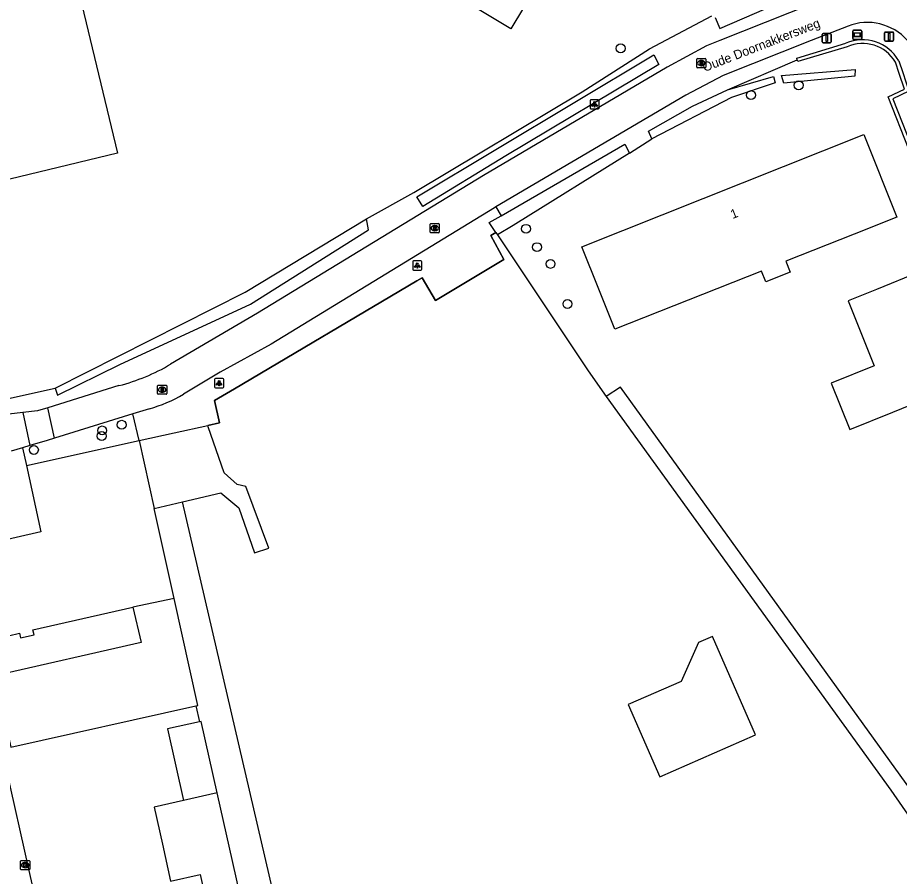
# Model space of a CAD drawing. Extents: x 164494 to 166241, y 382475 to 384494.
# Drawn here: x 164719.3 to 164815.9, y 383408.5 to 383502.5 of the extents above; entities that cross this region are included whole.
import ezdxf

# ---------------------------------------------------------------- set-up
doc = ezdxf.new("R2010")
doc.units = 0
for name, color, linetype in [('IMGEO_Afsluitpaal', 7, 'Continuous'), ('IMGEO_Boom', 7, 'Continuous'), ('IMGEO_Grasland_overig', 7, 'Continuous'), ('IMGEO_Groenvoorziening', 7, 'Continuous'), ('IMGEO_Haag', 7, 'Continuous'), ('IMGEO_Hek', 7, 'Continuous'), ('IMGEO_Kolk', 7, 'Continuous'), ('IMGEO_Lichtpunt', 7, 'Continuous'), ('IMGEO_Openbare_ruimte_label', 7, 'Continuous'), ('IMGEO_Pand', 7, 'Continuous'), ('IMGEO_Pand_nummerreeks', 7, 'Continuous'), ('IMGEO_Rijbaan_lokaal_open', 7, 'Continuous'), ('IMGEO_Rioolput', 7, 'Continuous'), ('IMGEO_Verklikker', 7, 'Continuous'), ('IMGEO_Voetpad_open', 7, 'Continuous'), ('IMGEO_Waterloop', 7, 'Continuous')]:
    doc.layers.add(name, color=color, linetype=linetype)

msp = doc.modelspace()

# ---------------------------------------------------------------- linework, layer by layer
at = {"layer": 'IMGEO_Afsluitpaal'}
for p, q in [((164807.533, 383500.752), (164808.323, 383500.752)), ((164808.323, 383500.752), (164807.533, 383500.752)), ((164814.269, 383500.022), (164814.269, 383500.822)), ((164814.269, 383500.822), (164814.269, 383500.022)), ((164814.369, 383500.922), (164815.159, 383500.922)), ((164815.159, 383500.922), (164814.369, 383500.922)), ((164815.259, 383500.822), (164815.259, 383500.022)), ((164815.259, 383500.022), (164815.259, 383500.822)), ((164807.433, 383499.852), (164807.433, 383500.652)), ((164807.433, 383500.652), (164807.433, 383499.852)), ((164808.423, 383500.652), (164808.423, 383499.852)), ((164808.423, 383499.852), (164808.423, 383500.652)), ((164815.159, 383499.922), (164814.369, 383499.922)), ((164814.369, 383499.922), (164815.159, 383499.922)), ((164808.323, 383499.752), (164807.533, 383499.752)), ((164807.533, 383499.752), (164808.323, 383499.752))]:
    msp.add_line(p, q, dxfattribs=at)
for points in [[(164814.689, 383500.797), (164814.839, 383500.797), (164814.839, 383500.047), (164814.689, 383500.047), (164814.689, 383500.797)], [(164807.853, 383500.627), (164808.003, 383500.627), (164808.003, 383499.877), (164807.853, 383499.877), (164807.853, 383500.627)]]:
    msp.add_lwpolyline(points, dxfattribs=at)
for centre, start, end in [((164807.533, 383500.652), 90, 180), ((164807.533, 383500.652), 90, 180), ((164808.323, 383500.652), 0, 90), ((164808.323, 383500.652), 360, 90), ((164814.369, 383500.822), 90, 180), ((164814.369, 383500.822), 90, 180), ((164815.159, 383500.822), 0, 90), ((164815.159, 383500.822), 360, 90), ((164807.533, 383499.852), 180, 270), ((164807.533, 383499.852), 180, 270), ((164808.323, 383499.852), 270, 0), ((164808.323, 383499.852), 270, 0), ((164814.369, 383500.022), 180, 270), ((164814.369, 383500.022), 180, 270), ((164815.159, 383500.022), 270, 0), ((164815.159, 383500.022), 270, 0)]:
    msp.add_arc(centre, 0.1, start, end, dxfattribs=at)
at = {"layer": 'IMGEO_Boom'}
for centre in [(164785.363, 383499.133), (164804.856, 383495.089), (164799.632, 383494.011), (164775.003, 383479.372), (164776.197, 383477.362), (164777.682, 383475.53), (164779.54, 383471.137), (164730.724, 383457.909), (164728.584, 383457.288), (164728.54, 383456.679), (164721.106, 383455.158)]:
    msp.add_circle(centre, 0.489, dxfattribs=at)
at = {"layer": 'IMGEO_Grasland_overig'}
for points in [[(164867.478, 383349.751), (164820.036, 383413.911), (164785.335, 383462.011), (164783.794, 383461.004)], [(164783.794, 383461.004), (164814.936, 383417.889), (164860.759, 383351.899)], [(164750.963, 383391.02), (164737.368, 383449.485)], [(164738.851, 383427.135), (164739.244, 383425.389)]]:
    msp.add_lwpolyline(points, dxfattribs=at)
at = {"layer": 'IMGEO_Groenvoorziening'}
for points in [[(164757.54, 383480.473), (164762.712, 383483.342), (164781.141, 383494.371), (164788.505, 383499.077), (164795.364, 383502.697)], [(164797.054, 383494.584), (164804.71, 383497.863)], [(164786.318, 383487.654), (164788.789, 383489.23)], [(164771.873, 383478.714), (164781.789, 383463.825), (164783.794, 383461.004)], [(164662.344, 383448.801), (164663.225, 383448.827), (164664.07, 383448.843), (164665.63, 383449.11), (164723.453, 383461.907)], [(164719.856, 383455.391), (164720.284, 383453.449)]]:
    msp.add_lwpolyline(points, dxfattribs=at)
at = {"layer": 'IMGEO_Haag'}
for points in [[(164804.71, 383497.863), (164804.648, 383498.068), (164810.02, 383499.694)], [(164810.159, 383499.318), (164804.764, 383497.685), (164804.71, 383497.863)], [(164817.327, 383479.981), (164817.068, 383480.286), (164819.267, 383482.152), (164814.665, 383493.821), (164816.44, 383494.67), (164815.874, 383496.362), (164815.456, 383497.612)], [(164815.822, 383497.777), (164816.253, 383496.489), (164816.931, 383494.462), (164815.174, 383493.621), (164819.744, 383482.032), (164817.327, 383479.981)]]:
    msp.add_lwpolyline(points, dxfattribs=at)
for centre, radius, start, end in [((164811.851, 383495.498), 4.578, 29.85172, 113.58083), ((164811.852, 383495.497), 4.179, 30.40254, 113.89317)]:
    msp.add_arc(centre, radius, start, end, dxfattribs=at)
at = {"layer": 'IMGEO_Hek'}
msp.add_lwpolyline([(164771.699, 383478.975), (164771.151, 383478.63), (164772.583, 383475.997), (164765.09, 383471.534), (164763.63, 383474.017), (164763.042, 383473.669), (164743.085, 383461.862), (164740.895, 383460.566), (164741.434, 383458.132), (164740.154, 383457.849)], dxfattribs=at)
at = {"layer": 'IMGEO_Kolk'}
for p, q in [((164719.648, 383409.262), (164719.648, 383410.114)), ((164719.723, 383410.188), (164720.575, 383410.188)), ((164720.649, 383410.114), (164720.649, 383409.262)), ((164720.575, 383409.188), (164719.723, 383409.188)), ((164720.159, 383409.408), (164720.134, 383409.408)), ((164720.136, 383409.968), (164720.161, 383409.968))]:
    msp.add_line(p, q, dxfattribs=at)
for points in [[(164719.648, 383409.262), (164719.648, 383410.114)], [(164719.723, 383410.188), (164720.575, 383410.188)], [(164720.649, 383410.114), (164720.649, 383409.262)], [(164720.575, 383409.188), (164719.723, 383409.188)], [(164719.969, 383409.888), (164720.092, 383409.888), (164720.092, 383409.737), (164720.222, 383409.888), (164720.386, 383409.888), (164720.24, 383409.737), (164720.393, 383409.488), (164720.241, 383409.488), (164720.156, 383409.652), (164720.092, 383409.585), (164720.092, 383409.488), (164719.969, 383409.488), (164719.969, 383409.888)]]:
    msp.add_lwpolyline(points, dxfattribs=at)
for centre, start, end in [((164719.725, 383410.112), 91.55205, 178.44795), ((164719.725, 383410.112), 91.55205, 178.44795), ((164720.573, 383410.112), 1.55205, 88.44795), ((164720.573, 383410.112), 1.55205, 88.44795), ((164719.725, 383409.264), 181.55205, 268.44795), ((164719.725, 383409.264), 181.55205, 268.44795), ((164720.573, 383409.264), 271.55205, 358.44795), ((164720.573, 383409.264), 271.55205, 358.44795)]:
    msp.add_arc(centre, 0.0765, start, end, dxfattribs=at)
for centre, major_axis, ratio, start_param, end_param in [((164720.135, 383409.688), (-0.387, 0.002), 0.722429, 4.712389, 7.853982), ((164720.16, 383409.688), (-0.39, 0.002), 0.717154, 1.570796, 4.712389)]:
    msp.add_ellipse(centre, major_axis=major_axis, ratio=ratio, start_param=start_param, end_param=end_param, dxfattribs=at)
at = {"layer": 'IMGEO_Lichtpunt'}
for p, q in [((164782.01, 383493.405), (164782.01, 383492.598)), ((164782.01, 383493.405), (164782.01, 383492.598)), ((164782.912, 383493.5), (164782.104, 383493.5)), ((164782.912, 383493.5), (164782.104, 383493.5)), ((164783.006, 383492.598), (164783.006, 383493.405)), ((164783.006, 383492.598), (164783.006, 383493.405)), ((164782.104, 383492.504), (164782.912, 383492.504)), ((164782.104, 383492.504), (164782.912, 383492.504)), ((164762.595, 383475.755), (164762.595, 383474.948)), ((164762.595, 383475.755), (164762.595, 383474.948)), ((164763.497, 383475.85), (164762.689, 383475.85)), ((164763.497, 383475.85), (164762.689, 383475.85)), ((164763.591, 383474.948), (164763.591, 383475.755)), ((164763.591, 383474.948), (164763.591, 383475.755)), ((164762.689, 383474.854), (164763.497, 383474.854)), ((164762.689, 383474.854), (164763.497, 383474.854)), ((164740.894, 383462.866), (164740.894, 383462.059)), ((164740.894, 383462.866), (164740.894, 383462.059)), ((164741.796, 383462.961), (164740.988, 383462.961)), ((164741.796, 383462.961), (164740.988, 383462.961)), ((164741.89, 383462.059), (164741.89, 383462.866)), ((164741.89, 383462.059), (164741.89, 383462.866)), ((164740.988, 383461.965), (164741.796, 383461.965)), ((164740.988, 383461.965), (164741.796, 383461.965))]:
    msp.add_line(p, q, dxfattribs=at)
for points in [[(164782.384, 383493.069), (164782.423, 383493.041), (164782.235, 383492.779), (164782.197, 383492.806), (164782.384, 383493.069)], [(164782.596, 383493.041), (164782.634, 383493.068), (164782.821, 383492.806), (164782.782, 383492.778), (164782.596, 383493.041)], [(164782.486, 383493.021), (164782.533, 383493.021), (164782.533, 383492.699), (164782.486, 383492.699), (164782.486, 383493.021)], [(164762.969, 383475.419), (164763.008, 383475.391), (164762.82, 383475.129), (164762.782, 383475.156), (164762.969, 383475.419)], [(164763.071, 383475.371), (164763.118, 383475.371), (164763.118, 383475.049), (164763.071, 383475.049), (164763.071, 383475.371)], [(164763.181, 383475.391), (164763.219, 383475.418), (164763.406, 383475.156), (164763.367, 383475.128), (164763.181, 383475.391)], [(164741.268, 383462.53), (164741.307, 383462.502), (164741.119, 383462.24), (164741.081, 383462.267), (164741.268, 383462.53)], [(164741.37, 383462.482), (164741.417, 383462.482), (164741.417, 383462.16), (164741.37, 383462.16), (164741.37, 383462.482)], [(164741.48, 383462.502), (164741.518, 383462.529), (164741.705, 383462.267), (164741.666, 383462.239), (164741.48, 383462.502)]]:
    msp.add_lwpolyline(points, dxfattribs=at)
for centre in [(164782.509, 383493.203), (164763.094, 383475.553), (164741.393, 383462.664)]:
    msp.add_circle(centre, 0.0994, dxfattribs=at)
for centre, start, end in [((164782.104, 383493.405), 90, 180), ((164782.104, 383493.405), 90, 180), ((164782.912, 383493.405), 0, 90), ((164782.912, 383493.405), 0, 90), ((164782.104, 383492.598), 180, 270), ((164782.104, 383492.598), 180, 270), ((164782.912, 383492.598), 270, 0), ((164782.912, 383492.598), 270, 360), ((164762.689, 383475.755), 90, 180), ((164762.689, 383475.755), 90, 180), ((164763.497, 383475.755), 0, 90), ((164763.497, 383475.755), 0, 90), ((164762.689, 383474.948), 180, 270), ((164762.689, 383474.948), 180, 270), ((164763.497, 383474.948), 270, 0), ((164763.497, 383474.948), 270, 360), ((164740.988, 383462.866), 90, 180), ((164740.988, 383462.866), 90, 180), ((164741.796, 383462.866), 0, 90), ((164741.796, 383462.866), 0, 90), ((164740.988, 383462.059), 180, 270), ((164740.988, 383462.059), 180, 270), ((164741.796, 383462.059), 270, 0), ((164741.796, 383462.059), 270, 360)]:
    msp.add_arc(centre, 0.0946, start, end, dxfattribs=at)
at = {"layer": 'IMGEO_Pand'}
for points in [[(164730.267, 383487.654), (164656.027, 383469.749), (164647.473, 383505.183), (164721.758, 383523.074), (164730.267, 383487.654)], [(164776.262, 383522.425), (164783.449, 383518.106), (164779.823, 383512.072), (164773.337, 383501.281), (164766.151, 383505.6), (164776.262, 383522.425)], [(164810.948, 383478.786), (164803.466, 383475.813), (164803.938, 383474.624), (164801.265, 383473.562), (164800.793, 383474.75), (164784.725, 383468.365), (164782.975, 383472.768), (164781.129, 383477.414), (164811.998, 383489.681), (164815.594, 383480.632), (164810.948, 383478.786)], [(164818.028, 383474.606), (164813.393, 383472.732), (164810.263, 383471.466), (164813.128, 383464.38), (164808.413, 383462.473), (164810.468, 383457.391), (164815.183, 383459.298), (164818.313, 383460.564), (164822.948, 383462.439), (164818.103, 383474.421)], [(164720.284, 383453.449), (164732.618, 383456.18)], [(164732.618, 383456.18), (164734.264, 383448.756)], [(164720.284, 383453.449), (164721.882, 383446.198), (164713.732, 383444.341), (164715.87, 383434.212), (164719.515, 383435.099), (164719.645, 383434.565), (164721.137, 383434.904), (164721.007, 383435.439), (164731.927, 383437.925)], [(164736.451, 383438.887), (164734.264, 383448.756)], [(164736.451, 383438.887), (164731.927, 383437.925)], [(164738.851, 383427.135), (164739.046, 383427.179), (164736.451, 383438.887)], [(164731.927, 383437.925), (164732.868, 383434.058), (164716.799, 383430.411), (164718.579, 383422.594), (164738.851, 383427.135)], [(164800.139, 383423.943), (164795.427, 383434.732), (164793.899, 383434.065), (164791.981, 383429.793), (164786.184, 383427.262), (164789.637, 383419.356), (164800.139, 383423.943)], [(164739.244, 383425.389), (164735.737, 383424.619), (164737.491, 383416.761)], [(164741.194, 383417.588), (164739.434, 383425.431), (164739.244, 383425.389)], [(164737.491, 383416.761), (164734.27, 383416.042), (164735.174, 383411.992), (164736.078, 383407.942), (164739.299, 383408.66), (164740.892, 383401.524)], [(164741.194, 383417.588), (164737.491, 383416.761)], [(164744.613, 383402.354), (164741.194, 383417.588)]]:
    msp.add_lwpolyline(points, dxfattribs=at)
at = {"layer": 'IMGEO_Rijbaan_lokaal_open'}
for points in [[(164808.828, 383505.036), (164796.221, 383500), (164794.753, 383499.407), (164790.471, 383497.065), (164770.361, 383485.201), (164745.588, 383470.135), (164736.073, 383464.54)], [(164810.262, 383501.572), (164806.227, 383500), (164796.587, 383496.145), (164792.485, 383494.012), (164771.708, 383481.781)], [(164771.708, 383481.781), (164771.534, 383481.679), (164747.101, 383466.722), (164741.488, 383463.681), (164737.479, 383461.248)], [(164730.422, 383462.201), (164722.622, 383459.776)], [(164719.895, 383459.238), (164717.739, 383458.983), (164712.427, 383457.585), (164708.916, 383456.753), (164693.004, 383452.936), (164678.342, 383449.582), (164665.421, 383446.666)], [(164722.622, 383459.776), (164721.503, 383459.428), (164719.895, 383459.238)], [(164719.895, 383459.238), (164720.68, 383455.635)], [(164723.35, 383456.437), (164722.622, 383459.776)], [(164733.751, 383459.673), (164731.926, 383459.105)], [(164731.926, 383459.105), (164723.35, 383456.437)], [(164723.35, 383456.437), (164722.557, 383456.19), (164720.68, 383455.635)], [(164719.856, 383455.391), (164718.625, 383455.027)], [(164720.68, 383455.635), (164719.856, 383455.391)], [(164704.135, 383380.45), (164714.062, 383382.757), (164725.993, 383385.33), (164723.274, 383397.213), (164720.675, 383408.755), (164718.016, 383420.672)]]:
    msp.add_lwpolyline(points, dxfattribs=at)
for centre, radius, start, end in [((164812.384, 383496.117), 5.853, 41.62554, 111.25429), ((164724.919, 383483.492), 21.991, 284.49179, 300.47843), ((164729.888, 383474.017), 14.855, 285.07406, 300.73197)]:
    msp.add_arc(centre, radius, start, end, dxfattribs=at)
at = {"layer": 'IMGEO_Rioolput'}
for p, q in [((164793.696, 383497.09), (164793.696, 383497.942)), ((164793.771, 383498.016), (164794.623, 383498.016)), ((164794.697, 383497.942), (164794.697, 383497.09)), ((164794.623, 383497.016), (164793.771, 383497.016)), ((164794.207, 383497.236), (164794.182, 383497.236)), ((164794.184, 383497.796), (164794.209, 383497.796)), ((164764.504, 383479.016), (164764.504, 383479.868)), ((164764.579, 383479.942), (164765.431, 383479.942)), ((164764.992, 383479.722), (164765.017, 383479.722)), ((164765.505, 383479.868), (164765.505, 383479.016)), ((164765.431, 383478.942), (164764.579, 383478.942)), ((164765.015, 383479.162), (164764.99, 383479.162)), ((164734.657, 383461.319), (164734.657, 383462.171)), ((164734.732, 383462.245), (164735.584, 383462.245)), ((164735.658, 383462.171), (164735.658, 383461.319)), ((164735.584, 383461.245), (164734.732, 383461.245)), ((164735.168, 383461.465), (164735.143, 383461.465)), ((164735.145, 383462.025), (164735.17, 383462.025))]:
    msp.add_line(p, q, dxfattribs=at)
for points in [[(164793.696, 383497.09), (164793.696, 383497.942)], [(164793.771, 383498.016), (164794.623, 383498.016)], [(164794.697, 383497.942), (164794.697, 383497.09)], [(164794.623, 383497.016), (164793.771, 383497.016)], [(164794.285, 383497.714), (164794.033, 383497.716), (164794.033, 383497.316)], [(164794.033, 383497.316), (164794.157, 383497.316), (164794.157, 383497.478), (164794.168, 383497.478)], [(164794.211, 383497.635), (164794.157, 383497.635), (164794.157, 383497.554)], [(164794.157, 383497.554), (164794.209, 383497.554)], [(164794.215, 383497.449), (164794.286, 383497.316), (164794.426, 383497.316), (164794.361, 383497.442)], [(164764.504, 383479.016), (164764.504, 383479.868)], [(164764.579, 383479.942), (164765.431, 383479.942)], [(164765.093, 383479.64), (164764.841, 383479.642), (164764.841, 383479.242)], [(164765.019, 383479.561), (164764.965, 383479.561), (164764.965, 383479.48)], [(164765.505, 383479.868), (164765.505, 383479.016)], [(164765.431, 383478.942), (164764.579, 383478.942)], [(164764.841, 383479.242), (164764.965, 383479.242), (164764.965, 383479.404), (164764.976, 383479.404)], [(164764.965, 383479.48), (164765.017, 383479.48)], [(164765.023, 383479.375), (164765.094, 383479.242), (164765.234, 383479.242), (164765.169, 383479.368)], [(164734.657, 383461.319), (164734.657, 383462.171)], [(164734.732, 383462.245), (164735.584, 383462.245)], [(164735.658, 383462.171), (164735.658, 383461.319)], [(164735.584, 383461.245), (164734.732, 383461.245)], [(164735.246, 383461.943), (164734.994, 383461.945), (164734.994, 383461.545)], [(164734.994, 383461.545), (164735.118, 383461.545), (164735.118, 383461.707), (164735.129, 383461.707)], [(164735.172, 383461.864), (164735.118, 383461.864), (164735.118, 383461.783)], [(164735.118, 383461.783), (164735.17, 383461.783)], [(164735.176, 383461.678), (164735.247, 383461.545), (164735.387, 383461.545), (164735.322, 383461.671)]]:
    msp.add_lwpolyline(points, dxfattribs=at)
for centre, radius, start, end in [((164793.773, 383497.94), 0.0765, 91.55205, 178.44795), ((164793.773, 383497.94), 0.0765, 91.55205, 178.44795), ((164794.621, 383497.94), 0.0765, 1.55205, 88.44795), ((164794.621, 383497.94), 0.0765, 1.55205, 88.44795), ((164793.773, 383497.092), 0.0765, 181.55205, 268.44795), ((164793.773, 383497.092), 0.0765, 181.55205, 268.44795), ((164794.167, 383497.425), 0.0533, 26.02933, 88.69889), ((164794.193, 383497.743), 0.19, 274.7715, 282.96867), ((164794.217, 383497.539), 0.0964, 77.00612, 93.18647), ((164794.231, 383497.596), 0.0378, 276.66336, 79.67722), ((164794.284, 383497.604), 0.109, 350.36119, 89.41601), ((164794.282, 383497.604), 0.112, 277.58423, 350.98172), ((164794.266, 383497.389), 0.108, 29.51342, 73.79051), ((164794.621, 383497.092), 0.0765, 271.55205, 358.44795), ((164794.621, 383497.092), 0.0765, 271.55205, 358.44795), ((164764.581, 383479.866), 0.0765, 91.55205, 178.44795), ((164764.581, 383479.866), 0.0765, 91.55205, 178.44795), ((164765.025, 383479.465), 0.0964, 77.00612, 93.18647), ((164765.039, 383479.522), 0.0378, 276.66336, 79.67722), ((164765.092, 383479.53), 0.109, 350.36119, 89.41601), ((164765.09, 383479.53), 0.112, 277.58423, 350.98172), ((164765.429, 383479.866), 0.0765, 1.55205, 88.44795), ((164765.429, 383479.866), 0.0765, 1.55205, 88.44795), ((164764.581, 383479.018), 0.0765, 181.55205, 268.44795), ((164764.581, 383479.018), 0.0765, 181.55205, 268.44795), ((164764.975, 383479.351), 0.0533, 26.02933, 88.69889), ((164765.001, 383479.669), 0.19, 274.7715, 282.96867), ((164765.074, 383479.315), 0.108, 29.51342, 73.79051), ((164765.429, 383479.018), 0.0765, 271.55205, 358.44795), ((164765.429, 383479.018), 0.0765, 271.55205, 358.44795), ((164734.734, 383462.169), 0.0765, 91.55205, 178.44795), ((164734.734, 383462.169), 0.0765, 91.55205, 178.44795), ((164735.582, 383462.169), 0.0765, 1.55205, 88.44795), ((164735.582, 383462.169), 0.0765, 1.55205, 88.44795), ((164734.734, 383461.321), 0.0765, 181.55205, 268.44795), ((164734.734, 383461.321), 0.0765, 181.55205, 268.44795), ((164735.128, 383461.654), 0.0533, 26.02933, 88.69889), ((164735.154, 383461.972), 0.19, 274.7715, 282.96867), ((164735.178, 383461.768), 0.0964, 77.00612, 93.18647), ((164735.192, 383461.825), 0.0378, 276.66336, 79.67722), ((164735.245, 383461.833), 0.109, 350.36119, 89.41601), ((164735.243, 383461.833), 0.112, 277.58423, 350.98172), ((164735.227, 383461.618), 0.108, 29.51342, 73.79051), ((164735.582, 383461.321), 0.0765, 271.55205, 358.44795), ((164735.582, 383461.321), 0.0765, 271.55205, 358.44795)]:
    msp.add_arc(centre, radius, start, end, dxfattribs=at)
for centre, major_axis, ratio, start_param, end_param in [((164794.183, 383497.516), (-0.387, 0.002), 0.722429, 4.712389, 7.853982), ((164794.208, 383497.516), (-0.39, 0.002), 0.717154, 1.570796, 4.712389), ((164764.991, 383479.442), (-0.387, 0.002), 0.722429, 4.712389, 7.853982), ((164765.016, 383479.442), (-0.39, 0.002), 0.717154, 1.570796, 4.712389), ((164735.144, 383461.745), (-0.387, 0.002), 0.722429, 4.712389, 7.853982), ((164735.169, 383461.745), (-0.39, 0.002), 0.717154, 1.570796, 4.712389)]:
    msp.add_ellipse(centre, major_axis=major_axis, ratio=ratio, start_param=start_param, end_param=end_param, dxfattribs=at)
at = {"layer": 'IMGEO_Verklikker'}
for p, q in [((164810.777, 383500.218), (164810.777, 383501.018)), ((164810.777, 383501.018), (164810.777, 383500.218)), ((164810.877, 383501.118), (164811.667, 383501.118)), ((164811.667, 383501.118), (164810.877, 383501.118)), ((164811.767, 383501.018), (164811.767, 383500.218)), ((164811.767, 383500.218), (164811.767, 383501.018)), ((164811.667, 383500.118), (164810.877, 383500.118)), ((164810.877, 383500.118), (164811.667, 383500.118))]:
    msp.add_line(p, q, dxfattribs=at)
for points in [[(164810.878, 383500.85), (164811.666, 383500.85), (164811.666, 383500.386), (164810.878, 383500.386), (164810.878, 383500.85)], [(164810.943, 383500.785), (164810.943, 383500.451), (164811.601, 383500.451), (164811.601, 383500.785), (164810.943, 383500.785)]]:
    msp.add_lwpolyline(points, dxfattribs=at)
for centre, start, end in [((164810.877, 383501.018), 90, 180), ((164810.877, 383501.018), 90, 180), ((164811.667, 383501.018), 0, 90), ((164811.667, 383501.018), 360, 90), ((164810.877, 383500.218), 180, 270), ((164810.877, 383500.218), 180, 270), ((164811.667, 383500.218), 270, 0), ((164811.667, 383500.218), 270, 0)]:
    msp.add_arc(centre, 0.1, start, end, dxfattribs=at)
at = {"layer": 'IMGEO_Voetpad_open'}
for points in [[(164771.708, 383481.781), (164772.275, 383480.798)], [(164771.699, 383478.975), (164770.982, 383480.051), (164772.275, 383480.798)], [(164740.154, 383457.849), (164741.434, 383458.132), (164740.895, 383460.566), (164743.085, 383461.862), (164763.042, 383473.669), (164763.63, 383474.017), (164765.09, 383471.534), (164772.583, 383475.997), (164771.151, 383478.63), (164771.699, 383478.975)], [(164732.618, 383456.18), (164731.926, 383459.105)], [(164732.618, 383456.18), (164736.455, 383457.03), (164740.154, 383457.849)], [(164737.368, 383449.485), (164741.582, 383450.474), (164743.549, 383448.824), (164745.27, 383443.883), (164746.846, 383444.411), (164744.321, 383451.166), (164743.354, 383451.363), (164741.949, 383452.648), (164740.206, 383457.698), (164740.154, 383457.849)], [(164734.264, 383448.756), (164737.368, 383449.485)]]:
    msp.add_lwpolyline(points, dxfattribs=at)
at = {"layer": 'IMGEO_Waterloop'}
for points in [[(164795.697, 383502.499), (164796.236, 383501.305), (164808.959, 383506.852)], [(164763.702, 383481.825), (164763.059, 383482.881), (164788.979, 383498.441), (164789.529, 383497.361), (164772.799, 383487.358), (164763.702, 383481.825)], [(164797.054, 383494.584), (164802.084, 383496.046), (164802.293, 383495.345), (164797.502, 383493.764), (164788.789, 383489.23)], [(164803.242, 383495.324), (164802.984, 383496.166), (164811.041, 383496.811), (164811.02, 383496.072), (164803.242, 383495.324)], [(164788.789, 383489.23), (164788.407, 383490.058), (164793.213, 383492.801), (164797.054, 383494.584)], [(164772.275, 383480.798), (164785.82, 383488.625), (164786.318, 383487.654)], [(164786.318, 383487.654), (164773.89, 383479.902), (164773.61, 383479.727), (164771.873, 383478.714)], [(164723.453, 383461.907), (164744.242, 383472.417), (164757.54, 383480.473)], [(164723.453, 383461.907), (164723.693, 383461.162), (164730.536, 383464.501), (164744.81, 383471.136), (164757.747, 383479.263), (164757.54, 383480.473)], [(164771.699, 383478.975), (164771.873, 383478.714)]]:
    msp.add_lwpolyline(points, dxfattribs=at)

# ---------------------------------------------------------------- texts
at = {"layer": 'IMGEO_Openbare_ruimte_label'}
msp.add_text('Oude Doornakkersweg', height=1, rotation=21.28017, dxfattribs=at).set_placement((164794.563, 383496.542))
at = {"layer": 'IMGEO_Pand_nummerreeks'}
msp.add_text('1', height=1, rotation=21.67499, dxfattribs=at).set_placement((164797.625, 383480.439))

doc.saveas('drawing.dxf')
